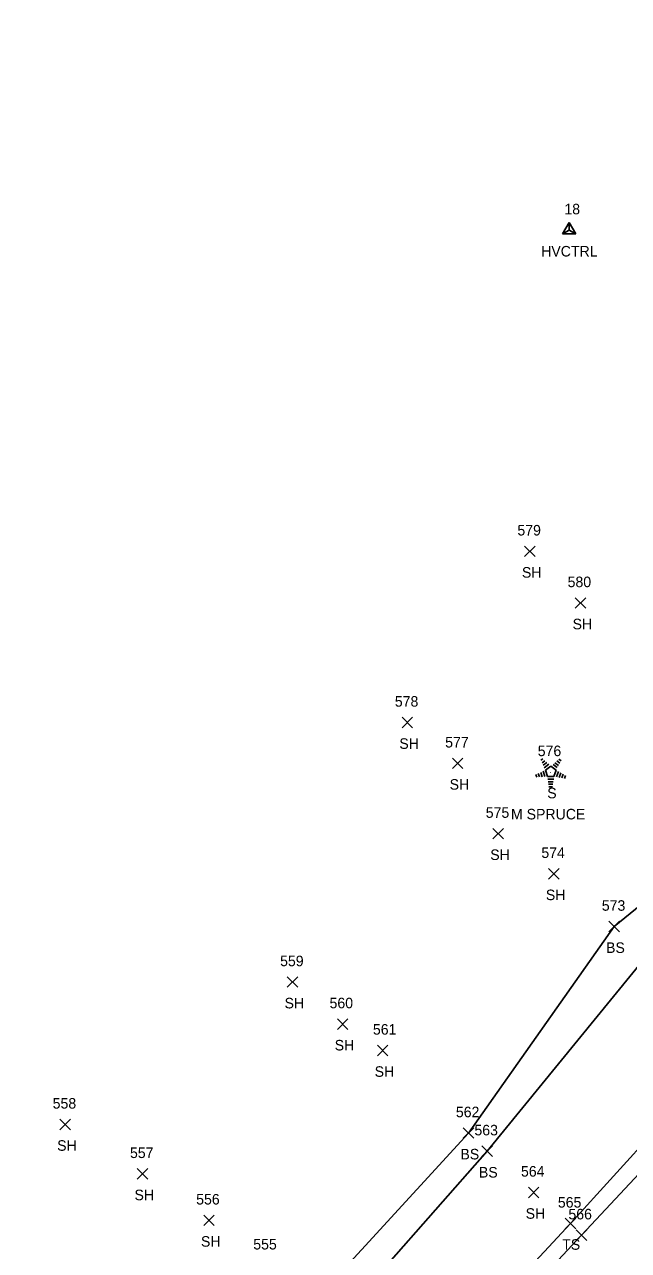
# Model space of a CAD drawing. Extents: x 1688195 to 1692013, y 424605 to 441234.
# Drawn here: x 1691404.7 to 1691519.2, y 439041.4 to 439274 of the extents above; entities that cross this region are included whole.
import ezdxf

# ---------------------------------------------------------------- set-up
doc = ezdxf.new("R2010")
doc.units = 0
for name, color, linetype in [('C_A', 7, 'Continuous'), ('C_I', 7, 'Continuous'), ('CPSM', 7, 'Continuous'), ('L_A', 7, 'Continuous'), ('L_C', 7, 'Continuous'), ('L_I', 7, 'Continuous'), ('L_TIC', 7, 'Continuous'), ('LELB', 7, 'Continuous'), ('LTC', 7, 'Continuous'), ('P_I', 7, 'Continuous'), ('P_TIC', 7, 'Continuous'), ('PET', 7, 'Continuous')]:
    doc.layers.add(name, color=color, linetype=linetype)

msp = doc.modelspace()

# ---------------------------------------------------------------- linework, layer by layer
at = {"layer": 'CPSM'}
for p, q in [((1691506.74, 439234.23), (1691507.99, 439236.39)), ((1691509.24, 439234.23), (1691507.99, 439236.39)), ((1691507.99, 439234.95), (1691507.99, 439236.39)), ((1691506.74, 439234.23), (1691507.99, 439234.95)), ((1691506.74, 439234.23), (1691509.24, 439234.23)), ((1691507.99, 439234.95), (1691507.99, 439234.95)), ((1691507.99, 439234.95), (1691509.24, 439234.23))]:
    msp.add_line(p, q, dxfattribs=at)
at = {"layer": 'L_TIC'}
for points in [[(1691499.54, 439173.02), (1691501.54, 439175.02)], [(1691501.54, 439173.02), (1691499.54, 439175.02)], [(1691509.15, 439163.22), (1691511.15, 439165.22)], [(1691511.15, 439163.22), (1691509.15, 439165.22)], [(1691476.29, 439140.55), (1691478.29, 439142.55)], [(1691478.29, 439140.55), (1691476.29, 439142.55)], [(1691485.83, 439132.8), (1691487.83, 439134.8)], [(1691487.83, 439132.8), (1691485.83, 439134.8)], [(1691493.54, 439119.46), (1691495.54, 439121.46)], [(1691495.54, 439119.46), (1691493.54, 439121.46)], [(1691504.08, 439111.85), (1691506.08, 439113.85)], [(1691506.08, 439111.85), (1691504.08, 439113.85)], [(1691515.55, 439101.83), (1691517.55, 439103.83)], [(1691517.55, 439101.83), (1691515.55, 439103.83)], [(1691454.52, 439091.31), (1691456.52, 439093.31)], [(1691456.52, 439091.31), (1691454.52, 439093.31)], [(1691464.03, 439083.33), (1691466.03, 439085.33)], [(1691466.03, 439083.33), (1691464.03, 439085.33)], [(1691471.6, 439078.33), (1691473.6, 439080.33)], [(1691473.6, 439078.33), (1691471.6, 439080.33)], [(1691411.37, 439064.3), (1691413.37, 439066.3)], [(1691413.37, 439064.3), (1691411.37, 439066.3)], [(1691487.91, 439062.66), (1691489.91, 439064.66)], [(1691489.91, 439062.66), (1691487.91, 439064.66)], [(1691491.43, 439059.22), (1691493.43, 439061.22)], [(1691493.43, 439059.22), (1691491.43, 439061.22)], [(1691426.03, 439054.92), (1691428.03, 439056.92)], [(1691428.03, 439054.92), (1691426.03, 439056.92)], [(1691500.25, 439051.4), (1691502.25, 439053.4)], [(1691502.25, 439051.4), (1691500.25, 439053.4)], [(1691438.65, 439046.1), (1691440.65, 439048.1)], [(1691440.65, 439046.1), (1691438.65, 439048.1)], [(1691507.26, 439045.52), (1691509.26, 439047.52)], [(1691509.26, 439045.52), (1691507.26, 439047.52)]]:
    msp.add_lwpolyline(points, dxfattribs=at)
at = {"layer": 'LELB'}
for points in [[(1691372.73, 438902.64), (1691398.57, 438929.63), (1691421.61, 438954.81), (1691450.5, 438984.08), (1691477.46, 439013.34), (1691508.26, 439046.52), (1691540.85, 439082.44), (1691568.31, 439110.72), (1691593.69, 439141.21), (1691622.93, 439171.73), (1691652.84, 439206.76), (1691674.71, 439229.19), (1691701.22, 439256.48), (1691710.89, 439279.75), (1691723.95, 439307.99), (1691712.17, 439332.07), (1691693.94, 439358.26), (1691684, 439373.02)], [(1691358.65, 438915.95), (1691383.88, 438942.54), (1691406.19, 438968.83), (1691432.09, 439000.43), (1691458.78, 439030.79), (1691488.91, 439063.66), (1691516.55, 439102.83), (1691546.52, 439127.21), (1691571.44, 439162.09), (1691585.36, 439179.75), (1691595.61, 439189.84), (1691598.8, 439192.56), (1691623.09, 439224.33), (1691645.87, 439250.99)], [(1691362.51, 438912.64), (1691386.93, 438940.67), (1691409.23, 438967.09), (1691436.47, 438996.99), (1691463, 439026.81), (1691492.43, 439060.22), (1691523.16, 439097.82), (1691549.35, 439125.66), (1691575.52, 439158.24), (1691588.61, 439176.65), (1691597.67, 439188.52), (1691599.59, 439192.01), (1691624.28, 439223.08), (1691646.72, 439249.94), (1691645.87, 439250.99)]]:
    msp.add_lwpolyline(points, dxfattribs=at)
at = {"layer": 'LTC'}
for p, q in [((1691502.64, 439134.37), (1691503, 439134.63)), ((1691502.85, 439133.9), (1691503.38, 439134.29)), ((1691503.06, 439133.44), (1691503.77, 439133.95)), ((1691503.27, 439132.97), (1691504.15, 439133.61)), ((1691505.3, 439133.91), (1691505.98, 439133.42)), ((1691505.67, 439134.26), (1691506.22, 439133.86)), ((1691506.04, 439134.61), (1691506.46, 439134.3)), ((1691501.68, 439131.65), (1691501.83, 439131.18)), ((1691502.13, 439131.86), (1691502.34, 439131.21)), ((1691502.59, 439132.08), (1691502.86, 439131.25)), ((1691503.04, 439132.3), (1691503.37, 439131.28)), ((1691503.5, 439132.52), (1691504.51, 439133.25)), ((1691503.5, 439132.52), (1691503.88, 439131.32)), ((1691505.11, 439131.32), (1691503.88, 439131.32)), ((1691504.51, 439133.25), (1691505.5, 439132.53)), ((1691504.93, 439133.56), (1691505.74, 439132.98)), ((1691505.5, 439132.53), (1691505.11, 439131.32)), ((1691505.94, 439132.26), (1691505.6, 439131.22)), ((1691506.39, 439132.01), (1691506.1, 439131.12)), ((1691506.83, 439131.76), (1691506.59, 439131.03)), ((1691507.28, 439131.5), (1691507.09, 439130.93)), ((1691505.08, 439130.82), (1691503.93, 439130.82)), ((1691504.99, 439130.32), (1691504, 439130.32)), ((1691504.91, 439129.82), (1691504.08, 439129.82)), ((1691504.82, 439129.32), (1691504.15, 439129.32))]:
    msp.add_line(p, q, dxfattribs=at)
at = {"layer": 'P_TIC'}
for points in [[(1691509.32, 439043.28), (1691511.32, 439045.28)], [(1691511.32, 439043.28), (1691509.32, 439045.28)]]:
    msp.add_lwpolyline(points, dxfattribs=at)
at = {"layer": 'PET'}
msp.add_lwpolyline([(1691375.46, 438899.9), (1691401.5, 438927.23), (1691424.19, 438951.44), (1691479.53, 439011.25), (1691510.32, 439044.28), (1691543.27, 439079.53), (1691570.24, 439108.89), (1691596.97, 439137.86), (1691630.02, 439173.34), (1691657.32, 439202.46), (1691678.85, 439225.99), (1691705.09, 439253.29), (1691720.65, 439270.18), (1691741.75, 439292.31), (1691750.04, 439301.33), (1691750.82, 439305.81), (1691750.97, 439309.53)], dxfattribs=at)

# ---------------------------------------------------------------- texts
at = {"layer": 'C_A'}
msp.add_text('HVCTRL', height=2, dxfattribs=at).set_placement((1691502.68, 439229.95))
at = {"layer": 'C_I'}
msp.add_text('18', height=2, dxfattribs=at).set_placement((1691507.09, 439237.95))
at = {"layer": 'L_A'}
for s, p in [('SH', (1691499.03, 439169.02)), ('SH', (1691508.64, 439159.22)), ('SH', (1691475.77, 439136.55)), ('SH', (1691485.32, 439128.8)), ('S', (1691503.83, 439127.16)), ('SH', (1691493.02, 439115.46)), ('SH', (1691503.57, 439107.85)), ('BS', (1691514.99, 439097.83)), ('SH', (1691454, 439087.31)), ('SH', (1691463.51, 439079.33)), ('SH', (1691471.09, 439074.33)), ('SH', (1691410.85, 439060.3)), ('BS', (1691487.36, 439058.66)), ('BS', (1691490.87, 439055.22)), ('SH', (1691425.52, 439050.92)), ('SH', (1691499.74, 439047.4)), ('SH', (1691438.14, 439042.1)), ('TS', (1691506.67, 439041.52))]:
    msp.add_text(s, height=2, dxfattribs=at).set_placement(p)
at = {"layer": 'L_C'}
msp.add_text('M SPRUCE', height=2, dxfattribs=at).set_placement((1691496.95, 439123.16))
at = {"layer": 'L_I'}
for s, p in [('579', (1691498.17, 439177.02)), ('580', (1691507.7, 439167.22)), ('578', (1691474.92, 439144.55)), ('577', (1691484.47, 439136.8)), ('576', (1691502.03, 439135.16)), ('575', (1691492.17, 439123.46)), ('574', (1691502.72, 439115.85)), ('573', (1691514.19, 439105.83)), ('559', (1691453.15, 439095.31)), ('560', (1691462.53, 439087.33)), ('561', (1691470.76, 439082.33)), ('558', (1691410, 439068.3)), ('562', (1691486.5, 439066.66)), ('563', (1691490.02, 439063.22)), ('557', (1691424.67, 439058.92)), ('564', (1691498.85, 439055.4)), ('556', (1691437.23, 439050.1)), ('565', (1691505.85, 439049.52)), ('555', (1691448.06, 439041.57))]:
    msp.add_text(s, height=2, dxfattribs=at).set_placement(p)
at = {"layer": 'LTC'}
msp.add_text('.', height=1.04, rotation=270, dxfattribs=at).set_placement((1691504.39, 439132.26))
at = {"layer": 'P_I'}
msp.add_text('566', height=2, dxfattribs=at).set_placement((1691507.85, 439047.28))

doc.saveas('drawing.dxf')
